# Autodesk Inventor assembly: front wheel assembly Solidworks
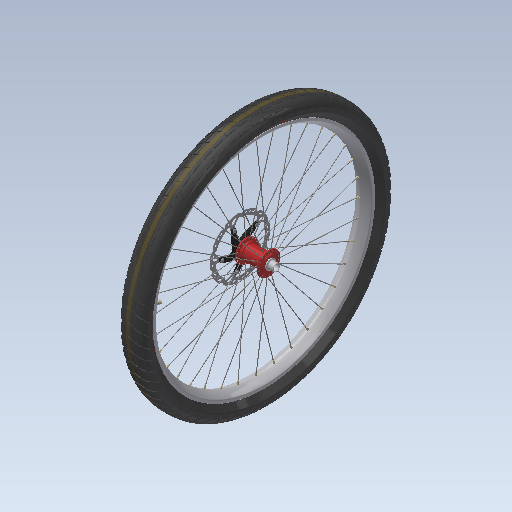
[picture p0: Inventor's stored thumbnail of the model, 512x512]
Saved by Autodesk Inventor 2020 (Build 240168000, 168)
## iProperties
Created: 2017-09
Part Number: front wheel assembly Solidworks
Material: Ogólny
Document SubType Name: Assembly
Designer: Tomasz
Sending System: SolidWorks 2017
Last Author: Tomasz
Last Saved: 2017-11-20
Author: Tomasz
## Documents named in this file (2)
- C:\Users\bruno\Documents\1-Cours-2020-21\1STI2D-2020-21\IT\6. Antivol\Inventor-Antivol\INVENTOR 2018_Steel Hardtail B+\front wheel assembly Solidworks.iam
- C:\Users\bruno\Documents\1-Cours-2020-21\1STI2D-2020-21\IT\6. Antivol\Inventor-Antivol\INVENTOR 2018_Steel Hardtail B+\Kopia front wheel assembly.iam^front wheel assembly Solidworks.iam
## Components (1 placed, 1 different names)
1. Kopia front wheel assembly.iam^front wheel assembly Solidworks:1 [sub-assembly]
